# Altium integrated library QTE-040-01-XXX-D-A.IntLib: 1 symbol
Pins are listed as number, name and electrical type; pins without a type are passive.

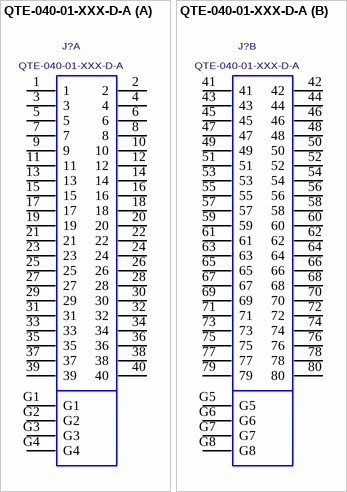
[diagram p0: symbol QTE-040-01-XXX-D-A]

## QTE-040-01-XXX-D-A
designator J?
HIGH SPEED TERMINAL STRIP, .8mm PITCH, 80 PINS.; MANUFACTURER: SAMTEC
footprint QTE-040-01-XXX-D-A
part A pins: 1, 2, 3, 4, 5, 6, 7, 8, 9, 10, 11, 12, 13, 14, 15, 16, 17, 18, 19, 20, 21, 22, 23, 24, 25, 26, 27, 28, 29, 30, 31, 32, 33, 34, 35, 36, 37, 38, 39, 40, G1, G2, G3, G4
part B pins: 41, 42, 43, 44, 45, 46, 47, 48, 49, 50, 51, 52, 53, 54, 55, 56, 57, 58, 59, 60, 61, 62, 63, 64, 65, 66, 67, 68, 69, 70, 71, 72, 73, 74, 75, 76, 77, 78, 79, 80, G5, G6, G7, G8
